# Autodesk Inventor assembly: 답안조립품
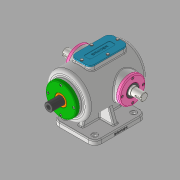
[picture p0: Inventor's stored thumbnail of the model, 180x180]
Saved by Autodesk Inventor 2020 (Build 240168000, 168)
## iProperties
Created: 2021-11
Part Number: 답안조립품
Document SubType Name: Assembly
Designer: Administrator
Author: Administrator
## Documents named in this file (14)
- C:\Users\Administrator\Desktop\711106V1025\답안조립품.iam
- C:\Users\Administrator\Desktop\711106V1025\본체.ipt
- C:\Users\Administrator\Desktop\711106V1025\베어링 6205.ipt
- 베어링 6205.ipt
- C:\Users\Administrator\Desktop\711106V1025\볼트 M4x0.7.ipt
- C:\Users\Administrator\Desktop\711106V1025\부시.ipt
- C:\Users\Administrator\Desktop\711106V1025\상부커버.ipt
- C:\Users\Administrator\Desktop\711106V1025\슬라이드 커버.ipt
- C:\Users\Administrator\Desktop\711106V1025\슬라이드.ipt
- C:\Users\Administrator\Desktop\711106V1025\오일실.ipt
- 오일실.ipt
- C:\Users\Administrator\Desktop\711106V1025\육각머리볼트 M4.ipt
- C:\Users\Administrator\Desktop\711106V1025\축 커버.ipt
- C:\Users\Administrator\Desktop\711106V1025\편심축.ipt
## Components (12 placed, 1 different names)
1. M4x0.7:3 — 각도:1
2. M4x0.7:4
3. M4x0.7:5
4. M4x0.7:6
5. M4x0.7:1 — 각도:2
6. M4x0.7:7
7. M4x0.7:8
8. M4x0.7:9
9. M4x0.7:2 — 각도:5
10. M4x0.7:10
11. M4x0.7:11
12. M4x0.7:12
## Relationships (3: Angle 3)
- 각도:1 [Angle]: M4x0.7:3
- 각도:2 [Angle]: M4x0.7:1
- 각도:5 [Angle]: M4x0.7:2
